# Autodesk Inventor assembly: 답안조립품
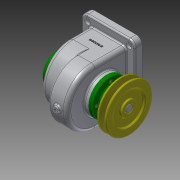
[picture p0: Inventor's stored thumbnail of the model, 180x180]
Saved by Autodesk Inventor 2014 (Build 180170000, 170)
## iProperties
Created: 2017-11
Part Number: 답안조립품
Document SubType Name: Assembly
Designer: user
Author: user
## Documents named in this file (14)
- C:\Users\user\Desktop\471108V1003\답안조립품.iam
- C:\Users\user\Desktop\471108V1003\축.ipt
- C:\Users\user\Desktop\471108V1003\키 - 5 x 5 x 18.ipt
- C:\Users\user\Desktop\471108V1003\키 - 6 x 6 x 22.ipt
- C:\Users\user\Desktop\471108V1003\V-벨트풀리.ipt
- C:\Users\user\Desktop\471108V1003\멈춤나사 - M4 x 10.ipt
- 멈춤나사 - M4 x 10.ipt
- C:\Users\user\Desktop\471108V1003\스퍼기어.ipt
- C:\Users\user\Desktop\471108V1003\베어링 6002.ipt
- C:\Users\user\Desktop\471108V1003\앞커버.ipt
- C:\Users\user\Desktop\471108V1003\오일 실 15 30 7.ipt
- C:\Users\user\Desktop\471108V1003\뒤커버.ipt
- C:\Users\user\Desktop\471108V1003\본채.ipt
- C:\Users\user\Desktop\471108V1003\볼트 M3 x 8.ipt
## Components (1 placed, 1 different names)
1. V-벨트풀리:1 — 각도:1
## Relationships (1: Angle 1)
- 각도:1 [Angle]: V-벨트풀리:1
